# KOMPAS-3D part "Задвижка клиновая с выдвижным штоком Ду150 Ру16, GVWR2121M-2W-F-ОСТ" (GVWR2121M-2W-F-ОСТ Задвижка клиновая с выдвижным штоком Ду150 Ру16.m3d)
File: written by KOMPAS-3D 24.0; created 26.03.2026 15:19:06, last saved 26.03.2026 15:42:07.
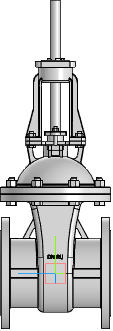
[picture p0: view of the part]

Document properties: Автор: R2D2; Полное имя файла: GVWR2121M-2W-F-ОСТ Задвижка клиновая с видвижным штоком Ду150 Ру16.cdw

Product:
- Part/product: Задвижка клиновая с выдвижным штоком Ду150 Ру16  | designation GVWR2121M-2W-F-ОСТ
    Масса: 60
    Раздел спецификации: Прочие изделия
    Форматы листов документа: A2
    Примечание: D040-10013
    additional columns: D040-10013

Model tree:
1. Операция без истории:1

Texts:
  GVWR2121M-2W-F-ОСТ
